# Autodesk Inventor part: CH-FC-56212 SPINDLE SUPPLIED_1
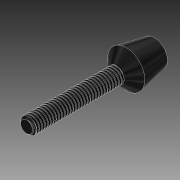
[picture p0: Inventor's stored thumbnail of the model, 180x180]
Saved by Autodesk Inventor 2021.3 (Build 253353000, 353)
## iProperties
Created: 2020-03
Part Number: CH-FC-56212 SPINDLE SUPPLIED_1
Material: Ogólny
Document SubType Name: Modeling
Designer: Przemyslaw Krecisz
Density: 1 g/cm^3
Appearance: Domyślna
Author: Przemyslaw Krecisz
Revision Number: ÈÎºÎ
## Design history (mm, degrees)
feature "Ðý×ª2"
node "Bryła1"
